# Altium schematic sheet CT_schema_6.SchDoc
size 365 x 245 mm
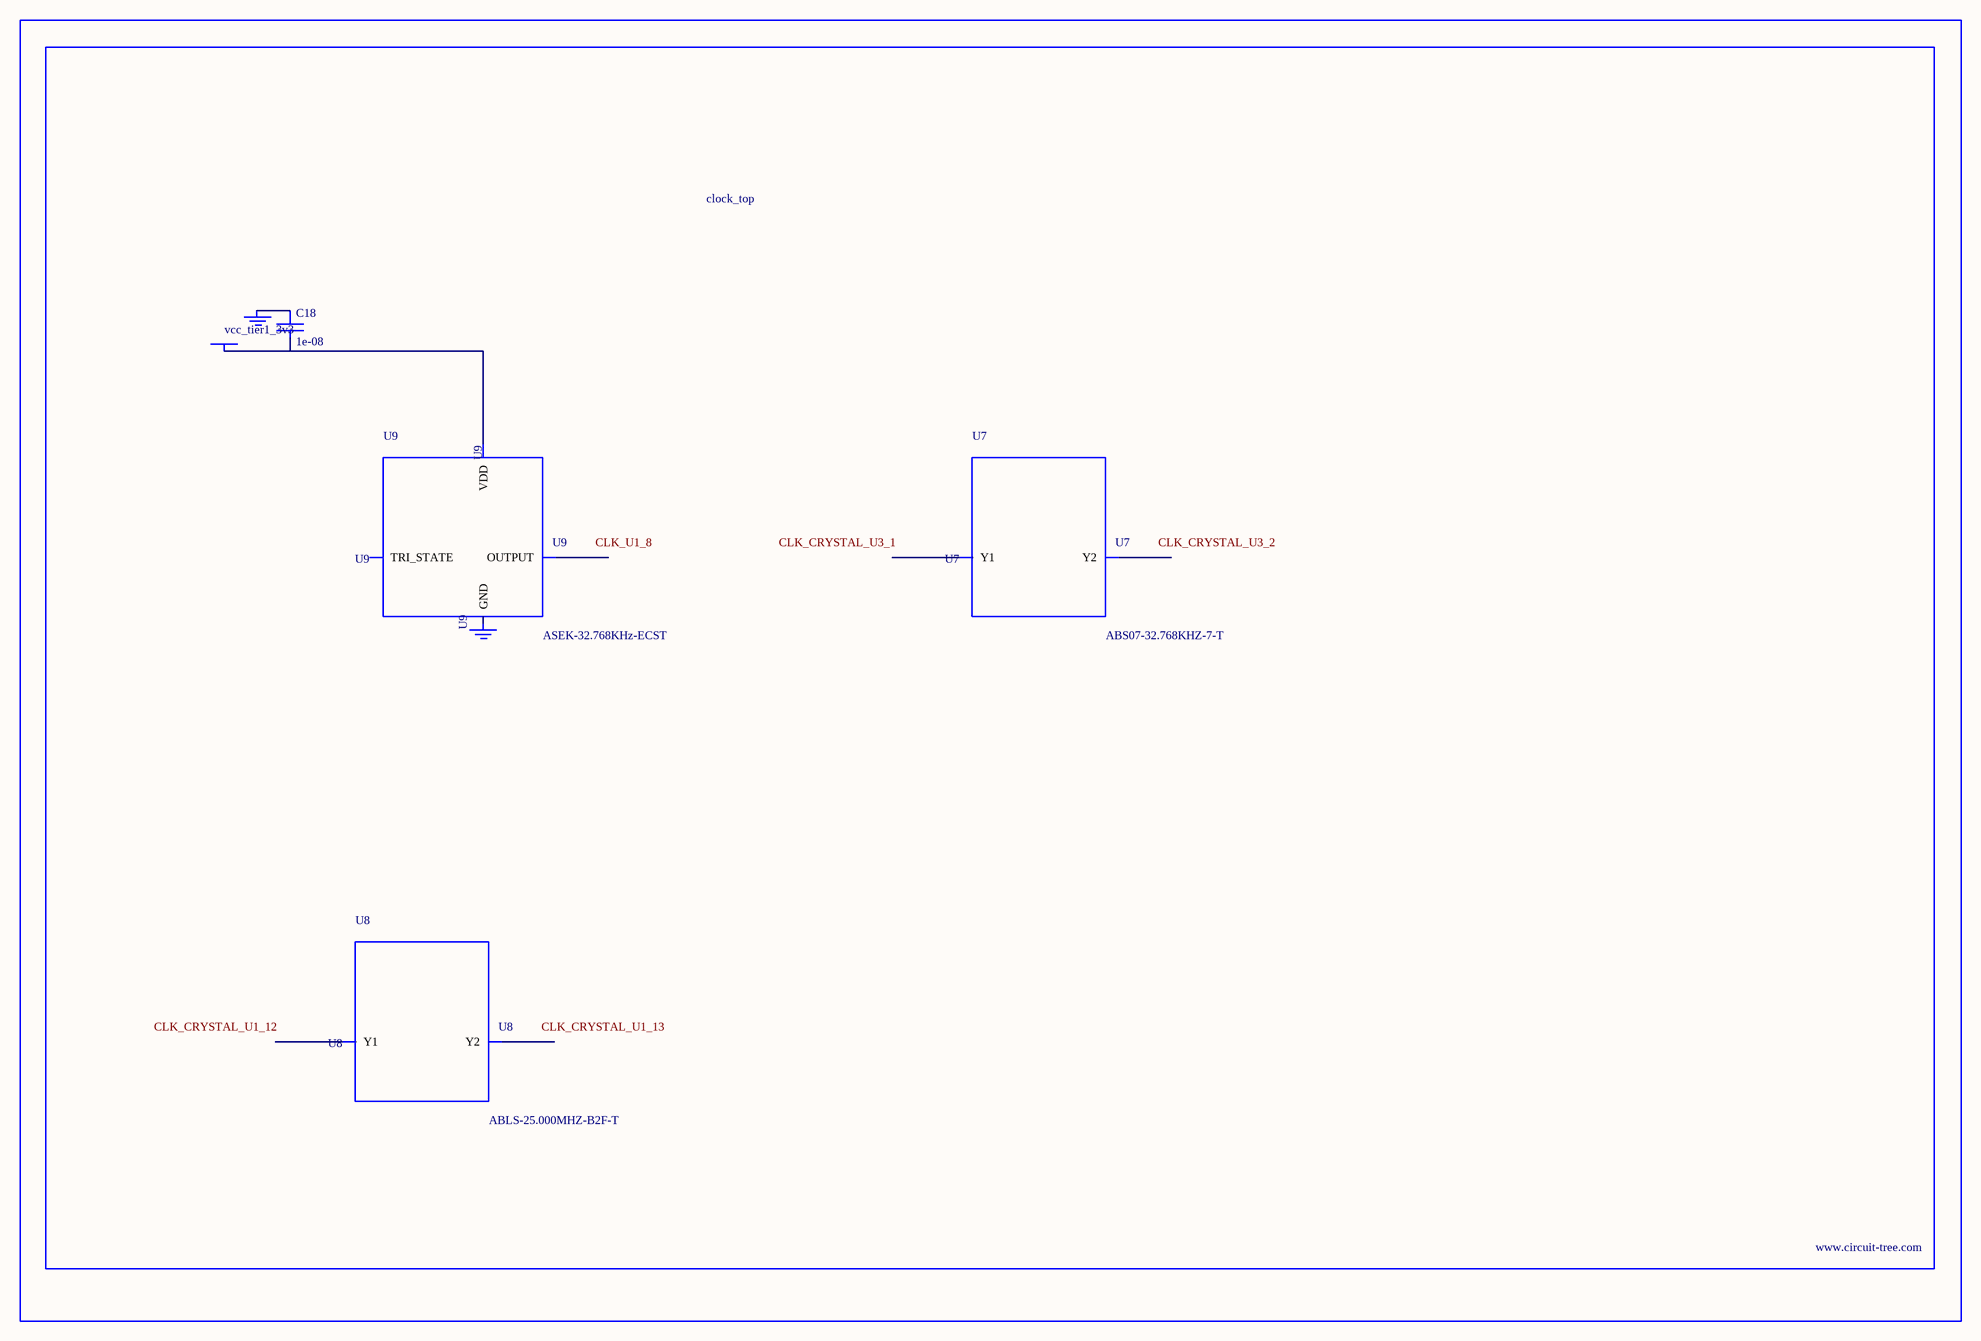
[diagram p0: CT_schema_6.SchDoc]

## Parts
BORDER5  (no value)
C18  1e-08  [C0402]
GND_INSTANCE_5_0  (no value)
GND_INSTANCE_5_1  (no value)
POWER_INSTANCE_5_0  vcc_tier1_3v3
U7  ABS07-32.768KHZ-7-T  [ABS07-32.768KHZ-7-T]
U8  ABLS-25.000MHZ-B2F-T  [ABLS-25.000MHZ-B2F-T]
U9  ASEK-32.768KHz-ECST  [ASEK]

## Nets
NetC18_1: C18.1 GND_INSTANCE_5_0.0(GND)
NetC18_2: C18.2 POWER_INSTANCE_5_0.0(PWR) U9.4(VDD)

Not connected (* = marked no-connect by the designer): GND_INSTANCE_5_1 0(GND); U7 1(Y1) 2(Y2); U8 1(Y1) 2(Y2); U9 1(TRI_STATE) 2(GND) 3(OUTPUT)

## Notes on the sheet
- Labels drawn without touching a wire or pin: CLK_CRYSTAL_U1_12, CLK_CRYSTAL_U1_13, CLK_CRYSTAL_U3_1, CLK_CRYSTAL_U3_2, CLK_U1_8

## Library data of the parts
BORDER5 = BORDER_PAGE5
C18 = C0402C103K3RAC
GND_INSTANCE_5_0 GND_INSTANCE_5_1 = GND
POWER_INSTANCE_5_0 = PWR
